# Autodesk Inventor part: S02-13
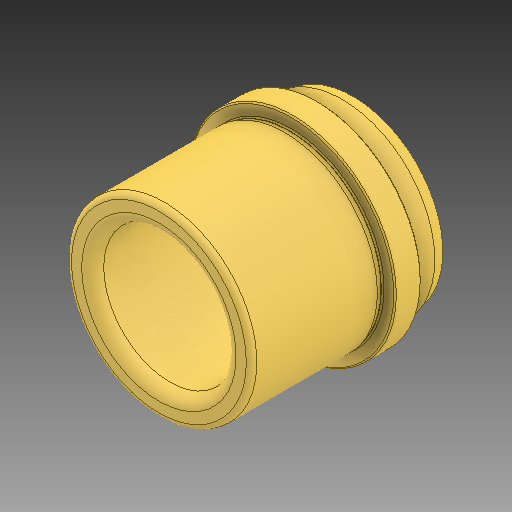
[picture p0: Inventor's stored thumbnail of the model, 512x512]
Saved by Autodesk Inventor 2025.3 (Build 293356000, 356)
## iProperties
Created: 2025-04
Part Number: S02-13
Material: Všeobecné
Document SubType Name: Modeling
Designer: Patrik
Density: 1 g/cm^3
Appearance: Výchozí
Description: Vodící pouzdro s nákružkem bezúdržbové
Stock Number: E 1105/30-36
Mass: 31.5799 g
Surface Area: 118.278 cm^2
Volume: 31.5799 cm^3
User Status: 2.0598
Author: Patrik
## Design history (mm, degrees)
feature "Base1"
node "Těleso1"
